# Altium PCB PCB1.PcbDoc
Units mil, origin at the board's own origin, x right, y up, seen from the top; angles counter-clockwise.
Board outline 3937.01 x 3346.46 mil, 2 copper layers (Top Layer, Bottom Layer); 14 components, 21 nets, 90 pads, 2 vias.
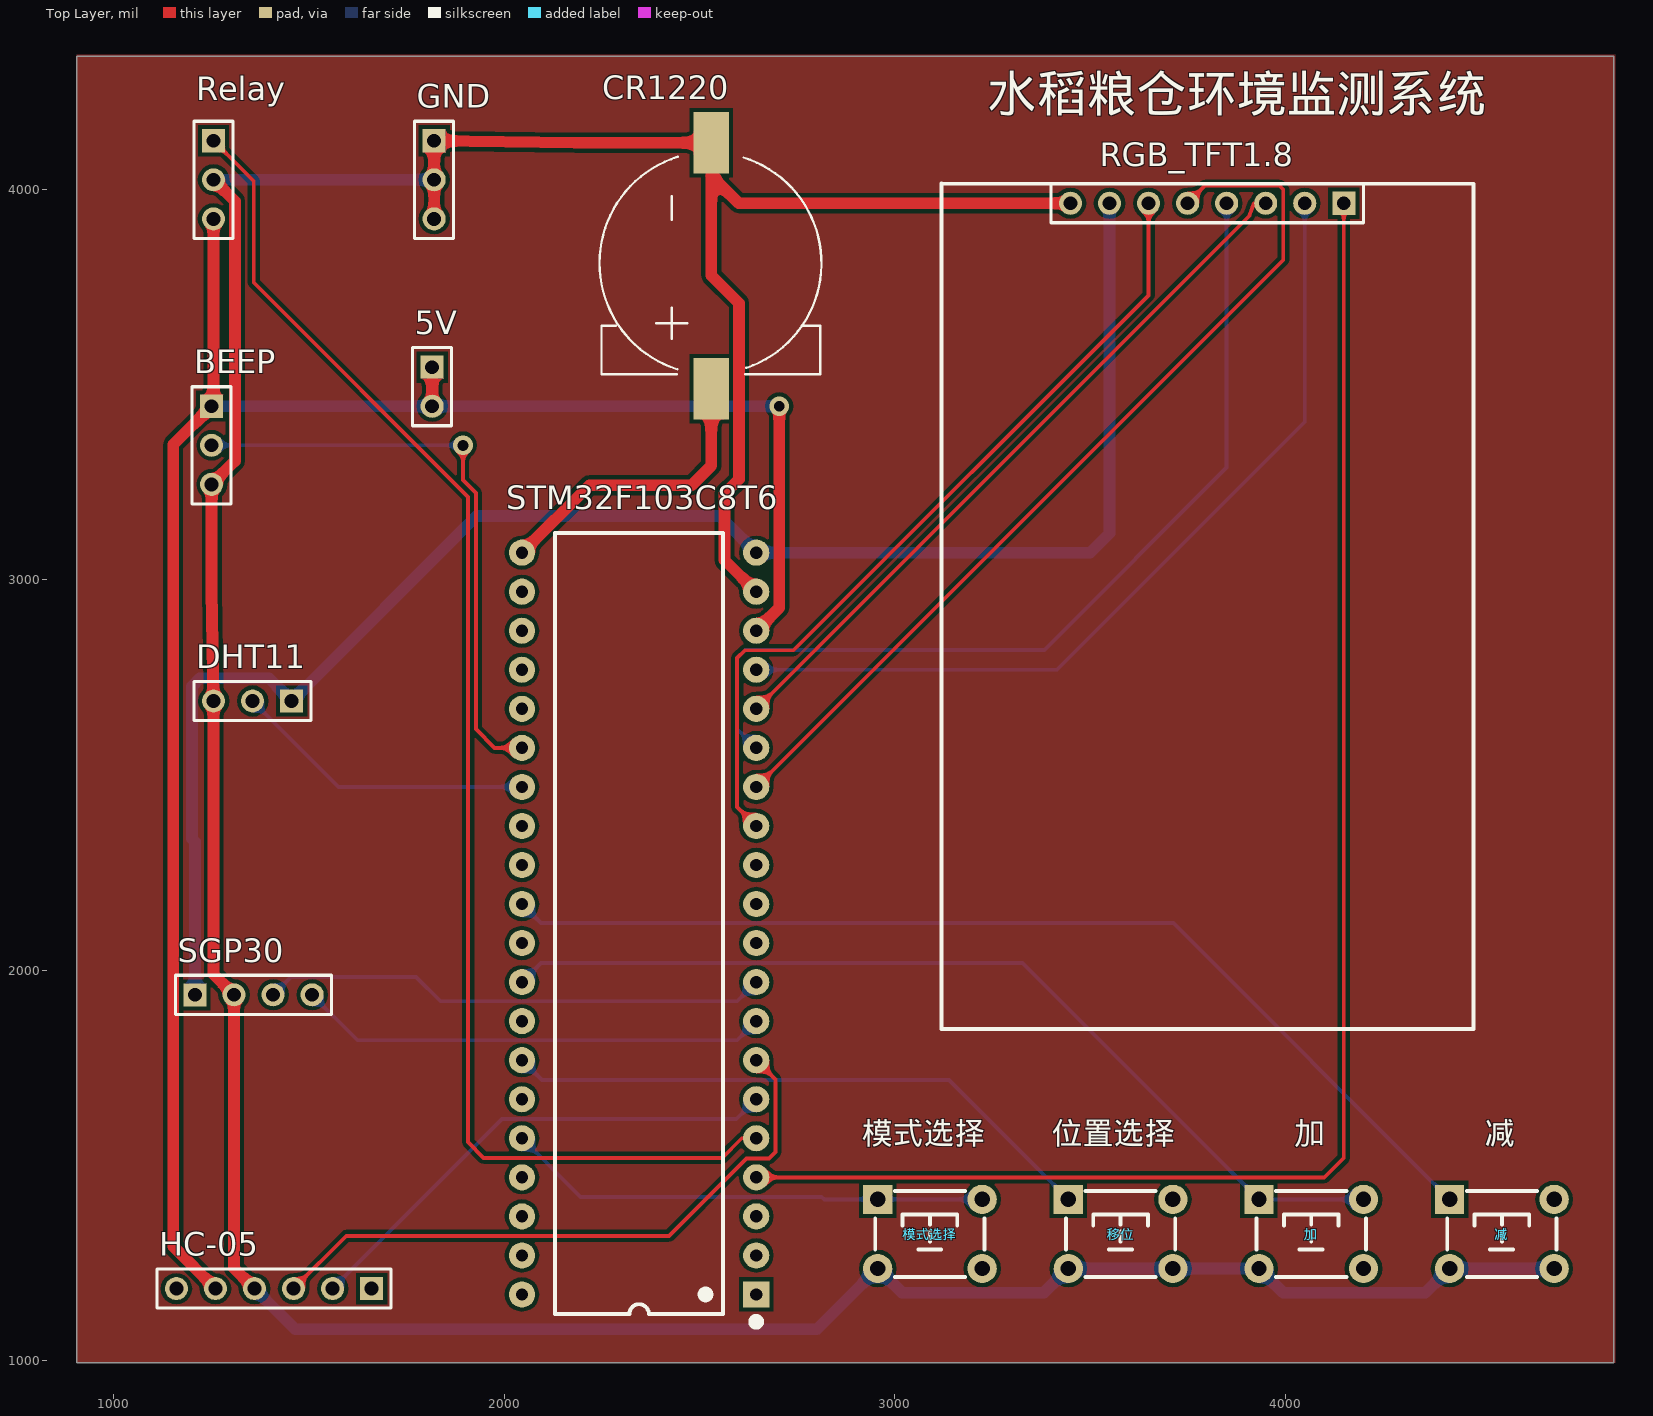
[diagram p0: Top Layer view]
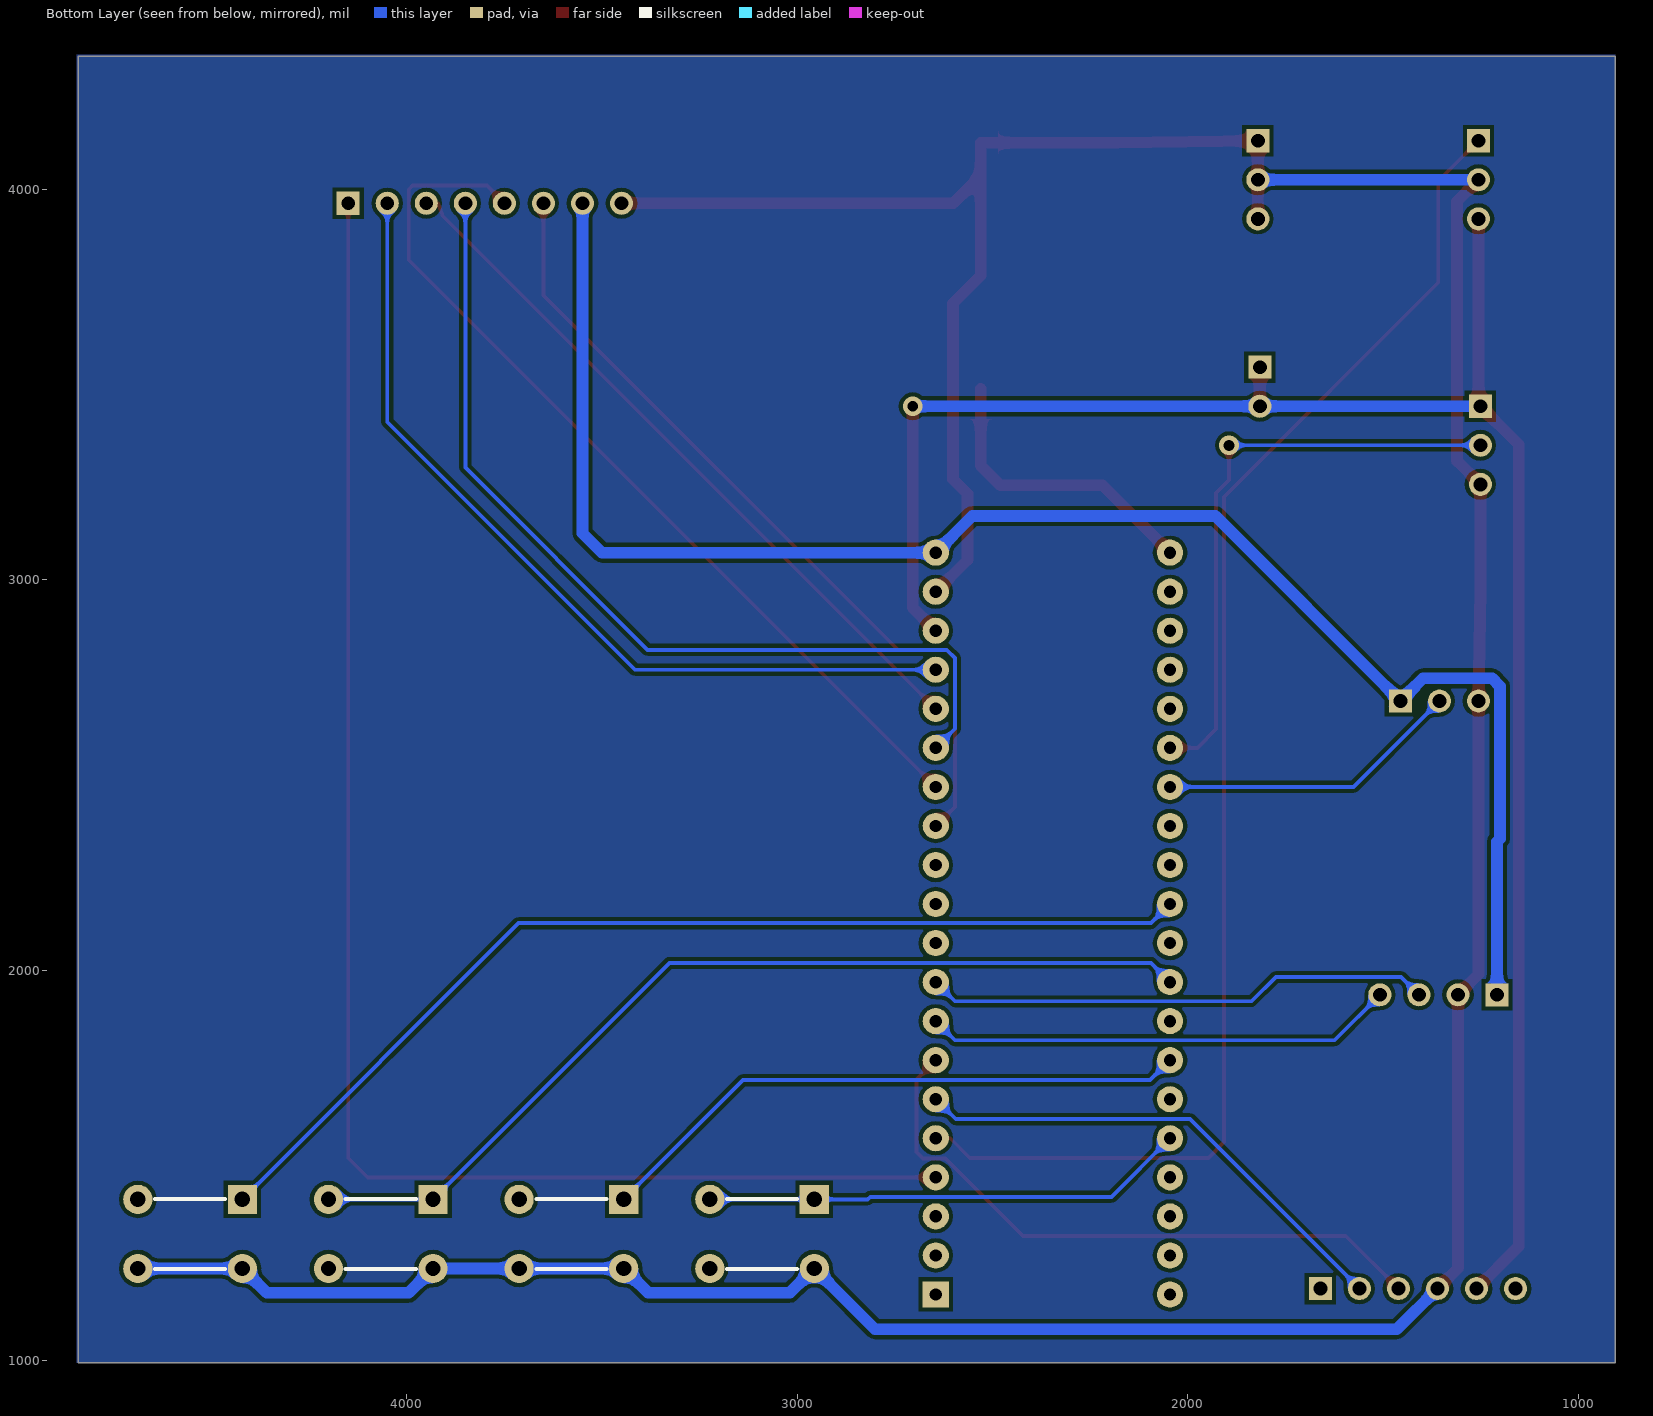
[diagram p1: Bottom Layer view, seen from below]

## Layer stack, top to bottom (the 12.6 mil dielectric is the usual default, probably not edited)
Top Solder: solder mask 0.4, Solder Resist, Dk 3.5
Top Layer: signal copper 1.4
Dielectric 1: dielectric 12.6, FR-4, Dk 4.8
Bottom Layer: signal copper 1.4
Bottom Solder: solder mask 0.4, Solder Resist, Dk 3.5

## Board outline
905,995 905,4341.46 4842.01,4341.46 4842.01,995

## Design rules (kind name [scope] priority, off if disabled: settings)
Clearance [All] p1: gap=10 ignorepadtopadclearanceinfootprint=FALSE except(0: Arc-Hole Track-Hole SMDPad-Hole THPad-Hole Via-Hole Fill-Hole Poly-Hole Region-Hole Text-Hole)
PolygonConnect [All] p1: connectstyle=Relief reliefconductorwidth=10 reliefentries=4 polygonreliefangle="90 Angle" airgapwidth=10
RoutingVias [All] p1: holewidth=28 width=50 viastyle="Through Hole" minholewidth=28 minwidth=50 maxholewidth=28 maxwidth=50
SolderMaskExpansion [All] p1: expansion=4
Width Power_All [InNetClass('Power Nets')] p1: maxlimit=30 minlimit=25 preferedwidth=30 minimp=50.000000 maximp=50.000000 favimp=50.000000
Width [All] p2: maxlimit=10 minlimit=10 preferedwidth=10
30 further rules are at their usual default settings.

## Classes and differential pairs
net class "Power Nets": 3.3V 5V GND VBAT

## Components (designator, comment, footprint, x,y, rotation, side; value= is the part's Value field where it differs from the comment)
5V "5V座子" HDR1X2 1815,3545 r270 top
BEEP "BEEP" HDR1X3 1250,3445 r270 top
CR1220 "CR1220" CR1220 2865,3395 r90 top
DHT11 "DHT11" HDR1X3 1455,2690 r180 top
GND "GND座子" HDR1X3 1820,4125 r270 top
HC-05 "HC-05" HDR1X6 1660,1185 r180 top
Relay "" HDR1X3 1255,4125 r270 top
RGB_TFT1.8 "RGB_TFT1.8" HDR1X8 4150,3965 r180 top
SGP30 "SGP30" HDR1X4 1207.5,1937.5 r0 top
STM32F103C8T6 "STM32F103C8T6" DIP40-600_MH 2345,2120 r180 top
减 "12x12x5" "TSW DIP-6*6*6" 4555,1325 r0 top
加 "12x12x5" "TSW DIP-6*6*6" 4066.67,1325 r0 top
模式选择 "12x12x5" "TSW DIP-6*6*6" 3090,1325 r0 top
移位 "12x12x5" "TSW DIP-6*6*6" 3578.33,1325 r0 top

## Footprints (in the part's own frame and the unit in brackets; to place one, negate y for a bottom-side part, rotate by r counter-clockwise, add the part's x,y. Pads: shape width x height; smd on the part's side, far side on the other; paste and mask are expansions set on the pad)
CR1220 [mm] "纽扣电池"
  rect 4x2.3 smd paste+0 mask+0.05: 1(2.413,8.509) 2(18.415,8.509)
  silkscreen extent 3.36,1.35 17.5,15.78
DIP40-600_MH [mm] "带底座 52*15.2*4mm(长宽高)"
  rect 1.7x1.7 hole 0.8: 1(-7.62,24.13)
  round 1.7 hole 0.8: 2(-7.62,21.59) 3(-7.62,19.05) 4(-7.62,16.51) 5(-7.62,13.97) 6(-7.62,11.43) 7(-7.62,8.89) 8(-7.62,6.35) 9(-7.62,3.81) 10(-7.62,1.27) 11(-7.62,-1.27) 12(-7.62,-3.81) 13(-7.62,-6.35) 14(-7.62,-8.89) 15(-7.62,-11.43) 16(-7.62,-13.97) 17(-7.62,-16.51) 18(-7.62,-19.05) 19(-7.62,-21.59) 20(-7.62,-24.13) 21(7.62,-24.13) 22(7.62,-21.59) 23(7.62,-19.05) 24(7.62,-16.51) 25(7.62,-13.97) 26(7.62,-11.43) 27(7.62,-8.89) 28(7.62,-6.35) 29(7.62,-3.81) 30(7.62,-1.27) 31(7.62,1.27) 32(7.62,3.81) 33(7.62,6.35) 34(7.62,8.89) 35(7.62,11.43) 36(7.62,13.97) 37(7.62,16.51) 38(7.62,19.05) 39(7.62,21.59) 40(7.62,24.13)
  silkscreen extent -7.87,-25.4 5.46,26.16, body extent -8.9,-26.18 8.9,26.18, height 8.3
HDR1X2 [mm] "Connector; Header; 2 Position"
  rect 1.5x1.5 hole 0.9: 1(0,0)
  round 1.5 hole 0.9: 2(2.54,0)
  silkscreen extent -1.27,-1.27 3.81,1.27
HDR1X3 [mm] "Connector; Header; 3 Position"
  rect 1.5x1.5 hole 0.9: 1(0,0)
  round 1.5 hole 0.9: 2(2.54,0) 3(5.08,0)
  silkscreen extent -1.27,-1.27 6.35,1.27
HDR1X4 [mm] "Connector; Header; 4 Position"
  rect 1.5x1.5 hole 0.9: 1(0,0)
  round 1.5 hole 0.9: 2(2.54,0) 3(5.08,0) 4(7.62,0)
  silkscreen extent -1.27,-1.27 8.89,1.27
HDR1X6 [mm] "Connector; Header; 6 Position"
  rect 1.5x1.5 hole 0.9: 1(0,0)
  round 1.5 hole 0.9: 2(2.54,0) 3(5.08,0) 4(7.62,0) 5(10.16,0) 6(12.7,0)
  silkscreen extent -1.27,-1.27 13.97,1.27
HDR1X8 [mm] "Connector; Header; 8 Position"
  rect 1.5x1.5 hole 0.9: 1(0,0)
  round 1.5 hole 0.9: 2(2.54,0) 3(5.08,0) 4(7.62,0) 5(10.16,0) 6(12.7,0) 7(15.24,0) 8(17.78,0)
  silkscreen extent -1.27,-1.27 19.05,1.27
"TSW DIP-6*6*6" [mm] "6*6*6mm"
  rect 1.9x1.9 hole 1: 1(-3.4,2.25)
  round 1.9 hole 1: 2(-3.4,-2.25) 3(3.4,-2.25) 4(3.4,2.25)
  silkscreen extent -3.56,-2.79 3.56,2.79, body extent -4.11,-3 4.11,3, height 5.95

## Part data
5V: library part "Header 2", "Header, 2-Pin"
BEEP DHT11 GND Relay: library part "Header 3", "Header, 3-Pin"
CR1220: "纽扣电池"
HC-05: library part "Header 6", "Header, 6-Pin"
RGB_TFT1.8: library part "Header 8", "Header, 8-Pin"
SGP30: library part "Header 4", "Header, 4-Pin"
STM32F103C8T6: "最小系统板"
减 加 模式选择 移位: library part "TSW DIP-12x12", "直插12x12轻触开关"

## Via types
v1: diameter 50, hole 28, Top Layer to Bottom Layer, 2 vias

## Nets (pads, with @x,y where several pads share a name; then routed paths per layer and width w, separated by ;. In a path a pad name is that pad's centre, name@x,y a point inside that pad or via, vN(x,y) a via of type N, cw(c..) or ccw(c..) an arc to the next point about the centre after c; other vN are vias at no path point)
3.3V: DHT11.1 RGB_TFT1.8.7 SGP30.1 STM32F103C8T6.20 | length 4276.9
  Bottom Layer w30: SGP30.1 1207.5,2329.5 1200,2337 1200,2728 1220,2748 1397,2748 DHT11.1 1929,3164 2551,3164 STM32F103C8T6.20 3500,3070 3550,3120 RGB_TFT1.8.7
5V: 5V.1 5V.2 BEEP.1 HC-05.5 Relay.3 STM32F103C8T6.18 | length 4980.8
  Top Layer w30: Relay.3 1255,3450 BEEP.1 1152,3347 1152,1293 HC-05.5 ; 5V.2 5V.1 ; STM32F103C8T6.18 2704,2929 v1(2704,3445)
  Bottom Layer w30: BEEP.1 5V.2 v1(2704,3445)
GND: BEEP.3 CR1220.2 DHT11.3 GND.1 GND.2 GND.3 HC-05.4 Relay.2 RGB_TFT1.8.8 SGP30.2 STM32F103C8T6.19 减.2 减.3 加.2 模式选择.2 移位.2 移位.3 | length 10123.4
  Top Layer w30: Relay.2 1310,3970 1310,3305 BEEP.3 1250,2973 DHT11.3 1255,1990 SGP30.2 1307.5,1237.5 HC-05.4 ; GND.3 GND.2 GND.1 2180,4120 CR1220.2 2530,4035 ; STM32F103C8T6.19 2563.76,3051.24 2563.76,3220.76 2601,3258 2601,3709 2530,3780 2530,4035 ; RGB_TFT1.8.8 2600,3965 2530,4035
  Bottom Layer w30: Relay.2 GND.2 ; HC-05.4 1464,1081 2800.72,1081 模式选择.2 3018.56,1174 3382.06,1174 移位.2 移位.3 加.2 3995.23,1174 4358.72,1174 减.2 减.3
PA1: BEEP.2 STM32F103C8T6.26 | length 1522.6
  Top Layer w10: v1(1894,3345) 1894,3256 1927,3223 1927,2618 1975,2570 STM32F103C8T6.26
  Bottom Layer w10: BEEP.2 v1(1894,3345)
PA2: DHT11.2 STM32F103C8T6.27 | length 781.1
  Bottom Layer w10: DHT11.2 1575,2470 STM32F103C8T6.27
PA5: STM32F103C8T6.30 减.1 | length 2689.5
  Bottom Layer w10: STM32F103C8T6.30 2094,2121 3713.72,2121 减.1
PA7: STM32F103C8T6.32 加.1 加.4 | length 2426.6
  Bottom Layer w10: STM32F103C8T6.32 2094,2019 3327.39,2019 加.1 加.4
PA8: Relay.1 STM32F103C8T6.5 | length 3610.3
  Top Layer w10: Relay.1 1358,4022 1358,3762 1907,3213 1907,1560 1947,1520 2558.07,1520 2608.07,1570 STM32F103C8T6.5
PA9: HC-05.2 STM32F103C8T6.6 | length 1285.9
  Bottom Layer w10: HC-05.2 1994,1619 2594,1619 STM32F103C8T6.6
PA10: HC-05.3 STM32F103C8T6.7 | length 1634.3
  Top Layer w10: HC-05.3 1595,1320 2421.53,1320 2620,1518.47 2677.47,1518.47 2694,1535 2694,1721 STM32F103C8T6.7
PA11: SGP30.4 STM32F103C8T6.8 | length 1206.1
  Bottom Layer w10: SGP30.4 1624,1821 2596,1821 STM32F103C8T6.8
PA12: SGP30.3 STM32F103C8T6.9 | length 1302.3
  Bottom Layer w10: SGP30.3 1453,1983 1774,1983 1836,1921 2596,1921 STM32F103C8T6.9
PB1: STM32F103C8T6.34 移位.1 | length 1547.1
  Bottom Layer w10: STM32F103C8T6.34 2096,1719 3139.06,1719 移位.1
PB5: RGB_TFT1.8.6 STM32F103C8T6.13 | length 2125.1
  Top Layer w10: STM32F103C8T6.13 2596,2419 2596,2800 2616,2820 2741,2820 3650,3729 RGB_TFT1.8.6
PB6: RGB_TFT1.8.5 STM32F103C8T6.14 | length 2357
  Top Layer w10: STM32F103C8T6.14 3995,3820 3995,4000 3985,4010 3795,4010 RGB_TFT1.8.5
PB7: RGB_TFT1.8.4 STM32F103C8T6.15 | length 2383.4
  Bottom Layer w10: STM32F103C8T6.15 2596,2619 2596,2800 2617,2821 3383,2821 3850,3288 RGB_TFT1.8.4
PB8: RGB_TFT1.8.3 STM32F103C8T6.16 | length 1850.3
  Top Layer w10: STM32F103C8T6.16 3908,3933 3920,3965 RGB_TFT1.8.3
PB9: RGB_TFT1.8.2 STM32F103C8T6.17 | length 2228
  Bottom Layer w10: STM32F103C8T6.17 3415,2770 4050,3405 RGB_TFT1.8.2
PB11: STM32F103C8T6.36 模式选择.1 模式选择.4 | length 1243.6
  Bottom Layer w10: STM32F103C8T6.36 2195,1420 2813,1420 2819.42,1413.58 模式选择.1 模式选择.4
PB15: RGB_TFT1.8.1 STM32F103C8T6.4 | length 3970.7
  Top Layer w10: STM32F103C8T6.4 4100,1470 4150,1520 RGB_TFT1.8.1
VBAT: CR1220.1 STM32F103C8T6.21 | length 774.4
  Top Layer w30: STM32F103C8T6.21 2218,3243 2480,3243 2530,3293 CR1220.1
pads on no net: HC-05.1 HC-05.6 STM32F103C8T6.1 STM32F103C8T6.2 STM32F103C8T6.3 STM32F103C8T6.10 STM32F103C8T6.11 STM32F103C8T6.12 STM32F103C8T6.22 STM32F103C8T6.23 STM32F103C8T6.24 STM32F103C8T6.25 STM32F103C8T6.28 STM32F103C8T6.29 STM32F103C8T6.31 STM32F103C8T6.33 STM32F103C8T6.35 STM32F103C8T6.37 STM32F103C8T6.38 STM32F103C8T6.39 STM32F103C8T6.40 减.4 加.3 模式选择.3 移位.4

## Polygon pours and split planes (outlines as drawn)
no net on Top Layer (solid, pour order 0): 905,4345 4845,4345 4845,995 905,995
no net on Bottom Layer (solid, pour order 2): 905,4345 4845,4345 4845,995 905,995

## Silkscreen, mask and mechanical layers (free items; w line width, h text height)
Top Overlay:
  lines w10: 3120,1849.65 4482.2,1849.65 4482.2,4015 3801.1,4015 3120,4015 ; 3120,1850 3120,4015.35
  text "水稻粮仓环境监测系统" at 3235,4170 h160
  text "位置选择" at 3401.73,1535.74 h100
  text "减" at 4510,1535.74 h100
  text "模式选择" at 2915,1535 h100
  text "加" at 4023.36,1535.37 h100
Mechanical 1:
  the board outline again, w10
